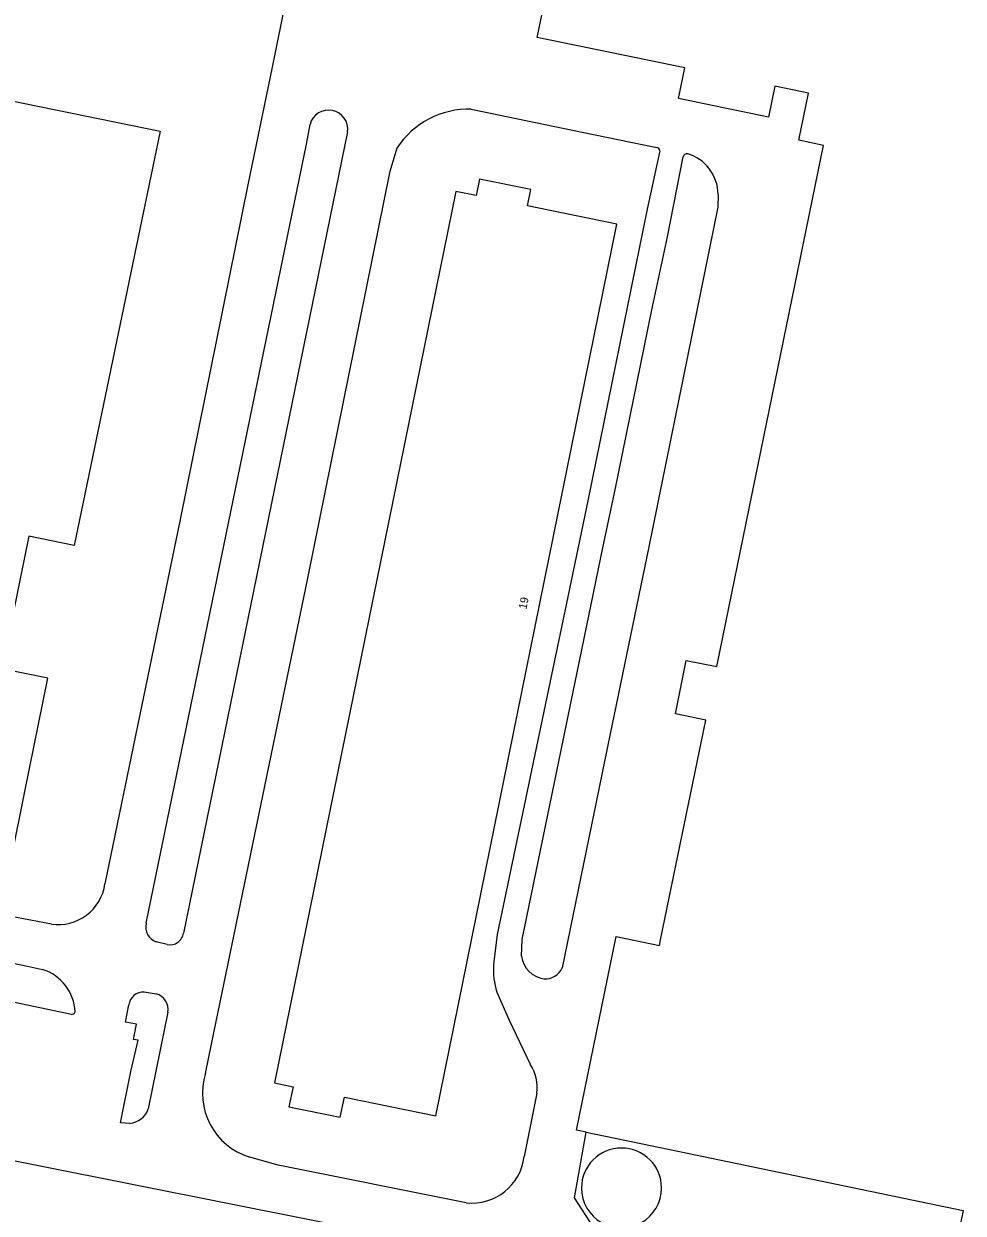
# Model space of a CAD drawing. Extents: x 157692 to 159670, y 381454 to 383289.
# Drawn here: x 157999.9 to 158117.3, y 382592.2 to 382740.9 of the extents above; entities that cross this region are included whole.
import ezdxf

# ---------------------------------------------------------------- set-up
doc = ezdxf.new("R2010")
doc.units = 0
for name, color, linetype in [('IMGEO_Opslagtank', 7, 'Continuous'), ('IMGEO_Pand', 7, 'Continuous'), ('IMGEO_Pand_nummerreeks', 7, 'Continuous'), ('IMGEO_Rijbaan_lokaal_gesloten', 7, 'Continuous')]:
    doc.layers.add(name, color=color, linetype=linetype)

msp = doc.modelspace()

# ---------------------------------------------------------------- linework, layer by layer
at = {"layer": 'IMGEO_Opslagtank'}
for start, end in [(0.0057, 179.9943), (179.9943, 0.0057)]:
    msp.add_arc((158074.58, 382595.34), 5, start, end, dxfattribs=at)
at = {"layer": 'IMGEO_Pand'}
for points in [[(158070.17, 382602.3), (158068.95, 382602.56), (158073.93, 382626.78), (158079.31, 382625.67), (158079.45, 382626.34), (158085.1, 382653.82), (158081.31, 382654.6), (158082.68, 382661.26), (158086.48, 382660.51), (158091.28, 382683.93), (158099.84, 382725.66), (158096.75, 382726.32), (158097.94, 382732.2), (158093.74, 382733.06), (158092.94, 382729.21), (158081.7, 382731.53), (158082.51, 382735.35), (158064.03, 382739.16), (158064.86, 382743.16)], [(157966.68, 382666.47), (157968.06, 382673.13), (157961.39, 382674.5), (157962.31, 382678.98), (157968.99, 382677.62), (157970.08, 382682.9), (157961.68, 382684.64), (157972.45, 382736.54), (157981.07, 382734.76), (157982.09, 382739.73), (157986.98, 382738.73), (157985.96, 382733.74), (158000, 382730.88), (158016.9, 382727.43), (158006.15, 382675.63), (158000.5, 382676.81), (158000, 382674.36), (157997.13, 382660.23)], [(158074.01, 382715.81), (158062.81, 382718.09), (158063.23, 382720.13), (158056.82, 382721.43), (158056.4, 382719.39), (158053.86, 382719.91), (158031.21, 382608.47), (158033.54, 382607.99), (158033.02, 382605.5), (158039.43, 382604.18), (158039.95, 382606.69), (158051.36, 382604.37), (158074.01, 382715.81)], [(157966.68, 382666.47), (157945.23, 382670.92), (157940.6, 382648.6), (157998.32, 382636.62), (158000, 382644.9), (158002.87, 382659.05), (158000, 382659.64), (157997.13, 382660.23)], [(158070.17, 382602.3), (158081.6, 382599.93), (158117.29, 382592.52), (158114.92, 382580.99)]]:
    msp.add_lwpolyline(points, dxfattribs=at)
at = {"layer": 'IMGEO_Rijbaan_lokaal_gesloten'}
for points in [[(158050.39, 382830.94), (158049.36, 382825.55), (158036.66, 382764.01), (158032.67, 382744.1), (158030.93, 382735.45), (158027.86, 382720.74), (158019.43, 382678.89), (158010.02, 382633.34)], [(158055.8, 382730.2), (158069.67, 382727.3), (158078.99, 382725.4)], [(158015.16, 382628.43), (158035.2, 382725.81), (158035.65, 382728.29)], [(158040.35, 382727.34), (158019.84, 382627.21)], [(158023.38, 382613.53), (158035.38, 382671.55), (158045.68, 382722.44), (158046.52, 382725.34)], [(158079.38, 382724.98), (158077.8, 382717.67), (158070.43, 382681.43), (158067.89, 382669.22), (158059.03, 382627.03), (158058.6, 382623.27)], [(158062.15, 382626.39), (158072.23, 382675.37), (158073.83, 382682.82), (158078.31, 382704.91), (158080.31, 382714.22), (158082.28, 382724.24)], [(158086.66, 382719.53), (158086.6, 382717.92), (158077.99, 382675.48), (158073.17, 382652.11), (158067.16, 382622.86)], [(158003.33, 382628.33), (157998.97, 382629.17), (157940.49, 382641.15), (157939.29, 382635.69), (158000.35, 382623.06), (158002.23, 382622.65)], [(158017.79, 382625.78), (158016.43, 382626.1)], [(158062.08, 382624.33), (158062.15, 382626.39)], [(158005.82, 382617.04), (157998.91, 382618.49), (157994.24, 382619.48), (157990.38, 382600.4), (158105.01, 382577.56), (158099.74, 382552.94)], [(158014.93, 382619.85), (158016.43, 382619.62)], [(158059.01, 382619.82), (158060.52, 382616.31), (158063.18, 382610.84)], [(158014.15, 382613.83), (158013.59, 382613.92), (158013.96, 382615.81), (158012.6, 382616.06), (158012.99, 382618.23)], [(158017.89, 382617.33), (158015.42, 382605.24)], [(158013.11, 382603.42), (158011.95, 382603.48), (158013.27, 382609.92), (158014.15, 382613.83)], [(158022.57, 382609.67), (158023.38, 382613.53)], [(158063.99, 382607.18), (158062.41, 382599.28)], [(158114.92, 382580.99), (158079.07, 382588.36), (158079.15, 382588.76), (158071.08, 382590.44), (158068.69, 382594.13), (158070.17, 382602.3)], [(158055.17, 382593.5), (158031.67, 382598.2), (158028.12, 382599.18)]]:
    msp.add_lwpolyline(points, dxfattribs=at)
for centre, radius, start, end in [((158055.54, 382719.4), 10.8, 88.625, 146.6761), ((158037.97, 382727.68), 2.4, 351.9667, 165.2539), ((158078.92, 382724.94), 0.463, 4.9051, 81.7173), ((158082.74, 382724.13), 0.475, 74.6577, 166.5205), ((158081.48, 382719.71), 5.07, 37.767, 74.1404), ((158081, 382719.36), 5.67, 1.6477, 37.585), ((158004.19, 382634.15), 5.88, 261.5748, 352.0991), ((158017.12, 382627.99), 2.01, 167.5093, 249.8014), ((158018.14, 382627.46), 1.72, 258.2404, 351.4315), ((158067.4, 382622.56), 8.83, 175.3847, 198.0716), ((158065.4, 382624.78), 3.35, 187.8351, 261.172), ((158000.5, 382617.12), 5.79, 2.3235, 72.6493), ((158065.06, 382623.74), 2.27, 265.4077, 337.4189), ((158014.85, 382617.96), 1.88, 87.7217, 171.9011), ((158015.88, 382617.66), 2.03, 350.6788, 74.4416), ((158005.88, 382617.46), 0.422, 261.9123, 345.2982), ((158030.61, 382607.22), 8.41, 163.0274, 252.7958), ((158058.52, 382607.88), 5.51, 352.7123, 32.435), ((158012.92, 382606.04), 2.63, 274.1645, 342.2855), ((158055.9, 382600.01), 6.55, 263.6423, 353.542)]:
    msp.add_arc(centre, radius, start, end, dxfattribs=at)

# ---------------------------------------------------------------- texts
at = {"layer": 'IMGEO_Pand_nummerreeks'}
msp.add_text('19', height=1, rotation=78.5124, dxfattribs=at).set_placement((158062.69, 382667.62))

doc.saveas('drawing.dxf')
